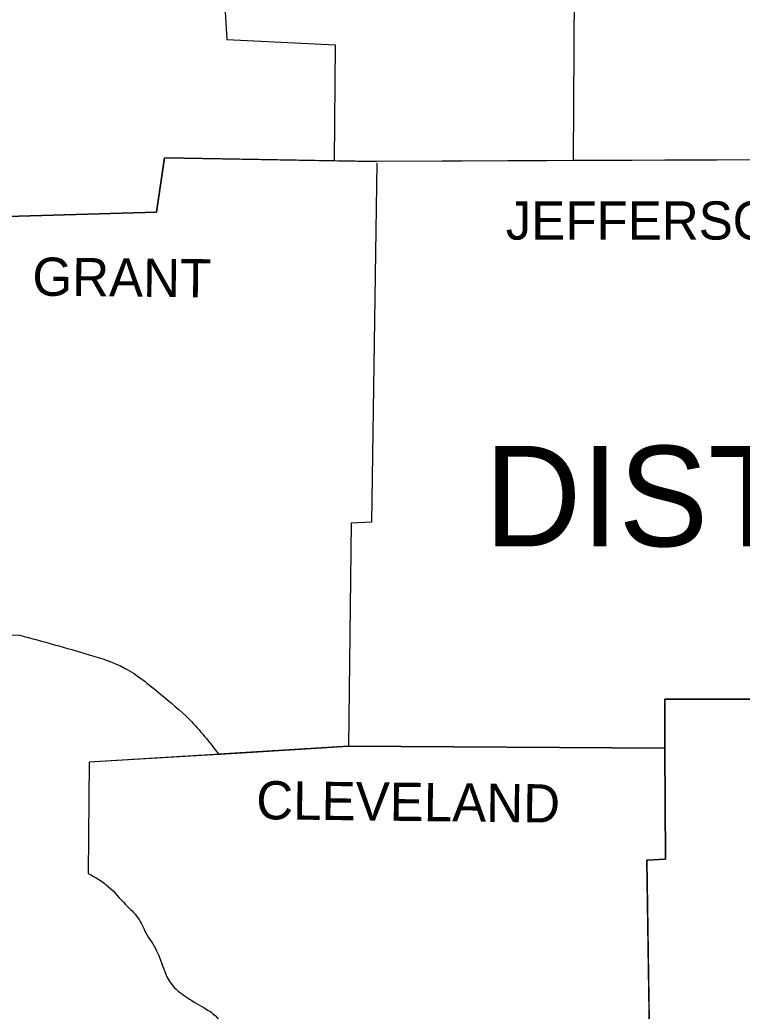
# Model space of a CAD drawing. Extents: x -12863 to 18921, y -8840 to 11152.
# Drawn here: x 13285 to 14081, y 6356 to 7447 of the extents above; entities that cross this region are included whole.
import ezdxf

# ---------------------------------------------------------------- set-up
doc = ezdxf.new("R2010")
doc.units = 0
for name, color, linetype in [('Level 1', 7, 'Continuous'), ('Level 2', 7, 'Continuous'), ('Level 3', 7, 'Continuous'), ('Level 48', 7, 'Continuous')]:
    doc.layers.add(name, color=color, linetype=linetype)

msp = doc.modelspace()

# ---------------------------------------------------------------- linework, layer by layer
at = {"layer": 'Level 1'}
for points in [[(13780.408528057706, 8074.393472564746), (13837.15612338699, 8070.47984524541), (13838.134530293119, 7696.7284411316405), (13787.257375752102, 7484.414161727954), (13895.860532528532, 7479.52212750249), (13894.844193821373, 7292.515822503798)], [(13018.229617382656, 7830.219821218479), (13134.660028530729, 7822.942920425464), (13130.74640124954, 7700.642068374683), (13258.917694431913, 7695.7500342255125), (13260.874508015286, 7589.103690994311), (13321.53573062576, 7584.211657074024), (13321.53573062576, 7565.621927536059), (13378.283326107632, 7561.708300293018), (13380.240139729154, 7493.219822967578), (13509.389839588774, 7493.219822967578), (13513.303466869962, 7425.709752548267), (13632.669098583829, 7419.83931172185), (13631.689211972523, 7292.454043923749)], [(14798.930024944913, 7405.163209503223), (14429.092247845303, 7414.947277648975), (14427.135434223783, 7294.603239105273), (13678.654218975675, 7291.668018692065)], [(13115.09189216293, 7162.518318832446), (13169.882673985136, 7170.345573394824), (13173.796301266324, 7203.611405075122), (13206.083726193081, 7209.481845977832), (13208.040539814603, 7229.049982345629), (13436.0093283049, 7235.898830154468), (13444.81498958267, 7295.581646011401), (13678.654218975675, 7291.668018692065)], [(13678.654218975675, 7289.711205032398), (13672.783778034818, 6894.434850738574), (13650.280421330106, 6893.456443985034), (13647.345200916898, 6647.876332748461)], [(12084.829513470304, 6880.7371554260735), (12082.87269988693, 6934.549530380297), (12098.527208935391, 6935.527937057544), (12108.311277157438, 7061.742416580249), (12258.985927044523, 7051.958348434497), (12255.072299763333, 6974.664209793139), (12449.775256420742, 6963.901734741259), (12450.75366332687, 6916.938207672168), (12626.866890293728, 6906.175732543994), (12657.1975017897, 6853.341764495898), (12638.607772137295, 6829.860000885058), (12647.413433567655, 6793.658948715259), (13285.334678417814, 6770.177185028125)], [(14291.136886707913, 6910.089359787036), (14282.331225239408, 6661.574028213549), (14259.827868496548, 6661.574028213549), (14255.914241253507, 6699.731894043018), (13995.658027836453, 6699.731894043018), (13995.658027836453, 6644.941112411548)], [(13647.345200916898, 6647.876332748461), (13504.497805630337, 6639.070671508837)], [(13647.345200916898, 6647.876332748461), (13995.658027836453, 6645.919519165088)], [(13995.658027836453, 6645.919519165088), (13996.63643474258, 6523.618667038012), (13976.089891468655, 6522.640260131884), (13981.960332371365, 6116.601431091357)], [(13506.454619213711, 6639.070671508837), (13361.650410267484, 6630.265010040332), (13360.672003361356, 6507.964157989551)]]:
    msp.add_lwpolyline(points, dxfattribs=at)
for points in [[(13285.334678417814, 6770.177185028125), (13361.650410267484, 6748.652235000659), (13400.786682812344, 6733.976132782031), (13439.92295554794, 6705.602335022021), (13472.210380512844, 6677.228537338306), (13504.497805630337, 6639.070671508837)], [(13360.672003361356, 6507.964157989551), (13383.175360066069, 6493.2880556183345), (13401.765089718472, 6473.719919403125), (13415.462785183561, 6459.0438170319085), (13424.268446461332, 6442.410901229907), (13436.0093283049, 6422.842764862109), (13452.6422441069, 6385.663305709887), (13467.318346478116, 6372.944017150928), (13487.864889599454, 6360.22472843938), (13500.584178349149, 6351.419067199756), (13513.303466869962, 6323.04526951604), (13519.173907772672, 6294.671471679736), (13529.936382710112, 6269.23289463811), (13534.82841685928, 6249.664758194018), (13526.022755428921, 6230.096621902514), (13524.065941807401, 6190.960349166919), (13529.936382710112, 6164.543365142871), (13537.763637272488, 6144.975228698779), (13542.655671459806, 6122.471871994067), (13539.72045089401, 6115.623024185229)]]:
    msp.add_spline(points, degree=3, dxfattribs=at)
at = {"layer": 'Level 48'}
for p, q in [((13095.515544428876, 6777.164392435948), (13285.334678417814, 6770.177185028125)), ((13995.658027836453, 6645.919519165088), (13995.658027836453, 6699.731894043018)), ((13995.658027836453, 6699.731894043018), (14255.914241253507, 6699.731894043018)), ((13647.345200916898, 6647.876332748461), (13506.44721154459, 6639.190840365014)), ((13995.658027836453, 6645.919519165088), (13647.345200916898, 6647.876332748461)), ((13647.345200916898, 6647.876332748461), (13995.658027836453, 6645.919519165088)), ((13980.036643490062, 6249.656578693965), (13976.089891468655, 6522.640260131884))]:
    msp.add_line(p, q, dxfattribs=at)
for points in [[(13678.654218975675, 7291.668018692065), (13631.689211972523, 7292.454043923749), (13444.81498958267, 7295.581646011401), (13436.0093283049, 7235.898830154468), (13208.040539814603, 7229.049982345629), (13206.083726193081, 7209.481845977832), (13173.796301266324, 7203.611405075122), (13169.882673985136, 7170.345573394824), (13115.09189216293, 7162.518318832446)], [(14299.075112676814, 7294.101041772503), (13894.844193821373, 7292.5158225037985), (13678.654218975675, 7291.668018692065)], [(13504.497805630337, 6639.070671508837), (13506.44721154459, 6639.190840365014), (13647.345200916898, 6647.876332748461)], [(13976.089891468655, 6522.640260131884), (13996.63643474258, 6523.618667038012), (13995.658027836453, 6645.919519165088)], [(13506.454619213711, 6639.070671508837), (13504.505015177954, 6638.952114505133), (13361.650410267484, 6630.265010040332), (13360.672003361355, 6507.96415798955)], [(13506.44721154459, 6639.190840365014), (13506.454619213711, 6639.070671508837)]]:
    msp.add_lwpolyline(points, dxfattribs=at)
for points in [[(13285.334678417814, 6770.177185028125), (13361.650410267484, 6748.652235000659), (13400.786682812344, 6733.976132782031), (13439.92295554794, 6705.602335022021), (13472.210380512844, 6677.228537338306), (13504.497805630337, 6639.070671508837)], [(13360.672003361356, 6507.964157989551), (13383.175360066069, 6493.2880556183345), (13401.765089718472, 6473.719919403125), (13415.462785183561, 6459.0438170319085), (13424.268446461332, 6442.410901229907), (13436.0093283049, 6422.842764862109), (13452.6422441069, 6385.663305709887), (13467.318346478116, 6372.944017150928), (13487.864889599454, 6360.22472843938), (13500.584178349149, 6351.419067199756), (13513.303466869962, 6323.04526951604), (13519.173907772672, 6294.671471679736), (13529.936382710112, 6269.23289463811), (13534.82841685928, 6249.664758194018), (13526.022755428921, 6230.096621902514), (13524.065941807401, 6190.960349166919), (13529.936382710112, 6164.543365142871), (13537.763637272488, 6144.975228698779), (13542.655671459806, 6122.471871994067), (13539.72045089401, 6115.623024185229)]]:
    msp.add_spline(points, degree=3, dxfattribs=at)

# ---------------------------------------------------------------- texts
at = {"layer": 'Level 2'}
msp.add_text('JEFFERSON', height=42.07344995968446, dxfattribs=at).set_placement((13820.523207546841, 7205.568218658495))
for s, height, rotation, p in [('GRANT', 42.07344995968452, 359.4031917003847, (13299.032373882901, 7143.928589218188)), ('CLEVELAND', 42.07344995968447, 359.33765002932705, (13545.590891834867, 6567.646973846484))]:
    msp.add_text(s, height=height, rotation=rotation, dxfattribs=at).set_placement(p)
at = {"layer": 'Level 3'}
msp.add_text('DISTRICT 2', height=110.55801354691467, dxfattribs=at).set_placement((13797.041443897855, 6868.0178667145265))

doc.saveas('drawing.dxf')
